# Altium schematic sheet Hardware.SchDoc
size 431 x 279 mm; Date: Not shown in title block; ApprovedBy: Not shown in title block; CheckedBy: Not shown in title block; Author: Not shown in title block; CompanyName: Not shown in title block; Engineer: Not shown in title block; Organization: Not shown in title block; Address1: Not shown in title block; Address2: Not shown in title block; Address3: Not shown in title block; Address4: Not shown in title block; DocumentNumber: 3; Revision: Use project parameter SCH_Rev; SheetNumber: 3; SheetTotal: 3; PageSetup: Record=PageOptions¦CenterHorizontal=True¦CenterVertical=True¦PrintScale=1.00¦XCorrection=1.00¦YCorrection=1.00¦PrintKind=0¦BorderSize=5000000¦LeftOffset=0¦BottomOffset=0¦Orientation=2¦PaperLength=1000¦PaperWidth=1000¦Scale=100¦PaperSource=15¦PrintQuality=600¦MediaType=1¦DitherType=10¦PaperKind=Letter¦PrintScaleMode=1
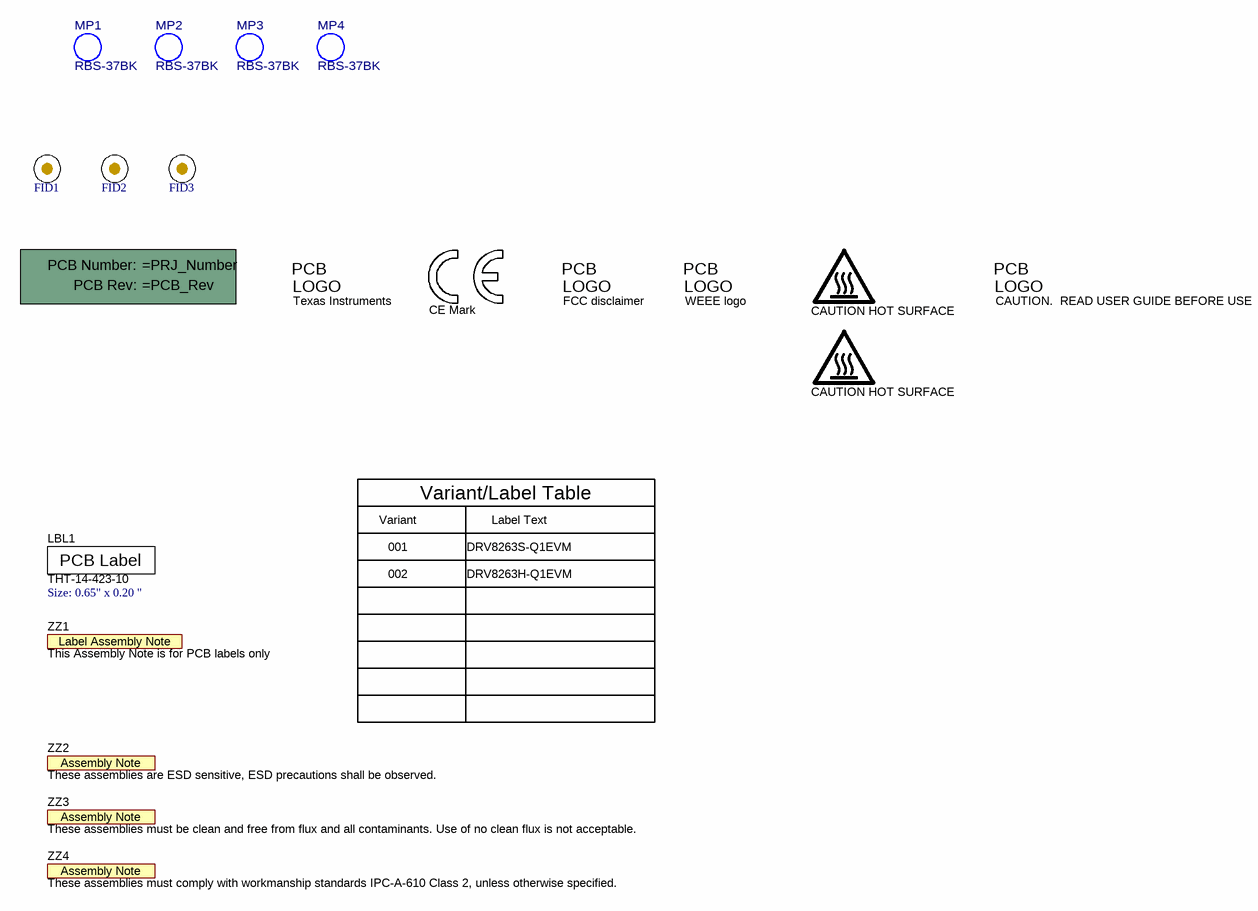
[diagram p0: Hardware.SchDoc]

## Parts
!PCB1  Printed Circuit Board  (value not drawn)  (mechanical)
FID1  Fiducial  [Fiducial10-20]  (value not drawn)  (no BOM)
FID2  Fiducial  [Fiducial10-20]  (value not drawn)  (no BOM)
FID3  Fiducial  [Fiducial10-20]  (value not drawn)  (no BOM)
LBL1  THT-14-423-10  Note: Size: 0.65" x 0.20 "  [Label_650x200]
Logo1  CE Mark  [CE_Mark_5mm]  (no BOM)
Logo2  Texas Instruments  [TI_Symbol_Overlay_Small]  (no BOM)
Logo3  FCC disclaimer  [FCC_disclaimer]  (no BOM)
Logo4  WEEE logo  [WEEE_Minimum]  (no BOM)
Logo5  CAUTION.  READ USER GUIDE BEFORE USE  [IEC_Caution_Small]  (no BOM)
LOGO6  CAUTION HOT SURFACE  [IEC_HotSurface_Small]  (no BOM)
LOGO7  CAUTION HOT SURFACE  [IEC_HotSurface_Small]  (no BOM)
MP1  RBS-37BK  [FP-RBS-37BK_BUMPER_CYLI-MFG]
MP2  RBS-37BK  [FP-RBS-37BK_BUMPER_CYLI-MFG]
MP3  RBS-37BK  [FP-RBS-37BK_BUMPER_CYLI-MFG]
MP4  RBS-37BK  [FP-RBS-37BK_BUMPER_CYLI-MFG]
ZZ1  This Assembly Note is for PCB labels only  [AssemblyNoteLabel]  (no BOM)
ZZ2  These assemblies are ESD sensitive, ESD precautions shall be observed.  [AssemblyNote]  (no BOM)
ZZ3  These assemblies must be clean and free from flux and all contaminants. Use of no clean flux is not acceptable.  [AssemblyNote]  (no BOM)
ZZ4  These assemblies must comply with workmanship standards IPC-A-610 Class 2, unless otherwise specified.  [AssemblyNote]  (no BOM)

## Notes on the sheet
- Variant
- Variant/Label Table
- Label Text
- 001
- 002
- DRV8263S-Q1EVM
- DRV8263H-Q1EVM

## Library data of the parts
!PCB1 = CMP-0003618-2: Manufacturer: Any
FID1-FID3 = CMP-0077181-1: Fiducial mark.  There is nothing to buy or mount.
LBL1 = CMP-0003625-1: Thermal Transfer Printable Labels, 0.650" W x 0.200" H - 10,000 per roll; Manufacturer: Brady
Logo1 = CMP-0074844-2: Manufacturer: Texas Instruments; SymbolCreator: a0412235; AEC Category: Q200; CompType: IC
Logo2 = CMP-0074838-1: Texas Instrument Corporate Signature; SymbolCreator: a0412235; Lib Reference: TI_Logo
Logo3 = CMP-0074847-1: FCC_disclaimer
Logo4 = CMP-0074769-4: Manufacturer: Texas Instruments; CompType: IC; AEC Category: Q200
Logo5 = CMP-0074836-1: IEC 61010-1 Caution Warning; SymbolCreator: a0412235; Lib Reference: IEC_Caution
LOGO6 LOGO7 = CMP-0074837-2: IEC 61010-1 Hot Surface Warning; Manufacturer: Texas Instruments; SymbolCreator: a0412235; CompType: IC; AEC Category: Q200
MP1-MP4 = CMP-0122650-1: Bumper Cylindrical, Dome 0.720" Dia (18.30mm) Polyurethane Black; Manufacturer: Essentra Components; AEC Qualified: No; SizeZ_mm: 14.7mm
ZZ1 = CMP-0003616-3
ZZ2 = CMP-0077236-1
ZZ3 = CMP-0077237-1
ZZ4 = CMP-0077238-1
